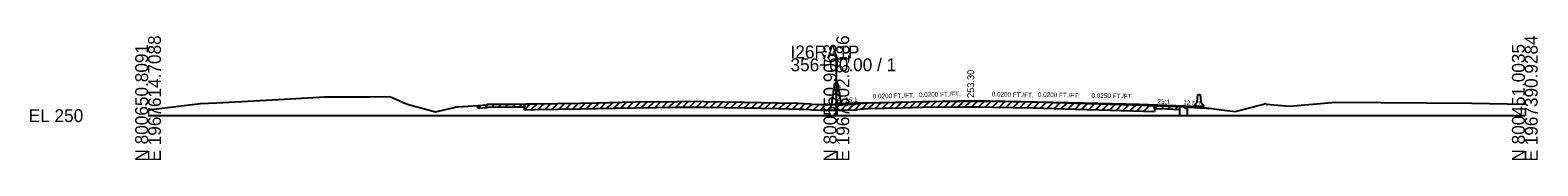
# Model space of a CAD drawing. Extents: x -26 to 304, y -10 to 7527.
# Drawn here: x -25.7 to 302.8, y 2990.3 to 3017.4 of the extents above; entities that cross this region are included whole.
import ezdxf

# ---------------------------------------------------------------- set-up
doc = ezdxf.new("R2010")
doc.units = 0
for name, color, linetype in [('Default', 7, 'Continuous'), ('RD_GPK_XS_Cell', 7, 'Continuous'), ('RD_XS_Base', 7, 'Continuous'), ('RD_XS_Box', 7, 'Continuous'), ('RD_XS_EarthShd', 7, 'Continuous'), ('RD_XS_ExGround', 7, 'Continuous'), ('RD_XS_ExPaveRet', 7, 'Continuous'), ('RD_XS_Misc_Line', 7, 'Continuous'), ('RD_XS_Pave', 7, 'Continuous'), ('RD_XS_PaveShd', 7, 'Continuous'), ('RD_XS_TX_Elev_EX', 7, 'Continuous'), ('RD_XS_TX_Elev_PR', 7, 'Continuous'), ('RD_XS_TX_Misc', 7, 'Continuous'), ('RD_XS_TX_MkPT', 7, 'Continuous'), ('RD_XS_TX_Profile', 7, 'Continuous'), ('RD_XS_TX_Station', 7, 'Continuous')]:
    doc.layers.add(name, color=color, linetype=linetype)

msp = doc.modelspace()

# ---------------------------------------------------------------- linework, layer by layer
at = {"layer": 'Default'}
for p, q in [((228, 3002.21), (228.58, 3003.04)), ((228.58, 3003.04), (228.75, 3004.62)), ((228.75, 3004.62), (229.25, 3004.62)), ((229.25, 3004.62), (229.42, 3003.04)), ((229.42, 3003.04), (230, 3002.21)), ((228, 3001.96), (228, 3002.21)), ((230, 3001.96), (228, 3001.96)), ((230, 3002.21), (230, 3001.96))]:
    msp.add_line(p, q, dxfattribs=at)
at = {"layer": 'RD_GPK_XS_Cell'}
for p, q in [((150, 3000), (150, 3012.48)), ((0, 3000), (150, 3000)), ((150, 3000), (300, 3000))]:
    msp.add_line(p, q, dxfattribs=at)
at = {"layer": 'RD_XS_Base'}
for p, q in [((150, 3002.42), (150, 3002.58)), ((224.72, 3000.13), (226.5, 3000.06)), ((226, 3001.56), (226, 3002.12)), ((226.5, 3001.54), (226, 3001.56)), ((226.5, 3000.06), (226.5, 3001.54))]:
    msp.add_line(p, q, dxfattribs=at)
at = {"layer": 'RD_XS_Box'}
for p, q in [((228, 3001.96), (230, 3001.8)), ((230, 3001.8), (231.8, 3001.58))]:
    msp.add_line(p, q, dxfattribs=at)
at = {"layer": 'RD_XS_EarthShd'}
for p, q in [((149, 3002.6), (149.67, 3007.08)), ((150, 3007.08), (149.67, 3007.08)), ((150, 3007.08), (150.33, 3007.08)), ((151, 3002.6), (150.33, 3007.08)), ((226, 3002.12), (228, 3001.96))]:
    msp.add_line(p, q, dxfattribs=at)
at = {"layer": 'RD_XS_ExGround'}
msp.add_lwpolyline([(0, 3001.21), (0.7, 3001.31), (11.42, 3002.61), (14.96, 3002.81), (29.71, 3003.57), (38.43, 3004.06), (47.23, 3004.1), (48.29, 3004.1), (52.66, 3004.16), (55.97, 3002.72), (56.73, 3002.39), (62.67, 3000.85), (66.68, 3001.79), (67.03, 3001.89), (67.59, 3001.92), (71.89, 3002.23), (73.85, 3002.37), (74.07, 3002.48), (79.41, 3002.52), (82.36, 3002.54), (84.3, 3002.56), (94.27, 3002.71), (97.71, 3002.79), (106.11, 3002.98), (115.33, 3003.09), (117.93, 3003.12), (121.25, 3003.07), (129.9, 3002.92), (137.34, 3002.78), (141.8, 3002.69), (142.82, 3002.65), (144.31, 3002.59), (144.57, 3002.5), (146.63, 3002.45), (148.22, 3002.41), (150, 3002.42), (150.63, 3002.42), (151.19, 3002.43), (154.21, 3002.53), (154.45, 3002.62), (155.13, 3002.66), (156.93, 3002.77), (164.02, 3002.95), (168.74, 3003.07), (177.62, 3003.15), (180.98, 3003.18), (184.24, 3003.12), (192.83, 3002.97), (202.08, 3002.69), (204.63, 3002.62), (207.15, 3002.54), (216.91, 3002.25), (222.09, 3002.08), (224.72, 3001.99), (225.56, 3001.94), (231.8, 3001.58), (233.94, 3001.27), (236.91, 3000.89), (243.12, 3002.53), (243.42, 3002.61), (243.65, 3002.48), (248.71, 3002.09), (258.85, 3002.96), (288.42, 3002.72), (300, 3002.47)], dxfattribs=at)
at = {"layer": 'RD_XS_ExPaveRet'}
for p, q in [((71.89, 3001.6), (71.89, 3002.23)), ((71.89, 3001.6), (73.85, 3001.75)), ((73.85, 3001.75), (74.07, 3001.86)), ((74.07, 3001.86), (79.41, 3001.89)), ((79.41, 3001.89), (82, 3001.91)), ((82, 3001.28), (82, 3002.53)), ((82, 3002.53), (82, 3001.91)), ((82, 3001.28), (82.36, 3001.29)), ((82.36, 3001.29), (84.3, 3001.31)), ((84.3, 3001.31), (94.27, 3001.46)), ((94.27, 3001.46), (97.71, 3001.54)), ((97.71, 3001.54), (106.11, 3001.73)), ((106.11, 3001.73), (115.33, 3001.84)), ((115.33, 3001.84), (117.93, 3001.87)), ((117.93, 3001.87), (121.25, 3001.82)), ((121.25, 3001.82), (129.9, 3001.67)), ((129.9, 3001.67), (137.34, 3001.53)), ((137.34, 3001.53), (141.8, 3001.44)), ((141.8, 3001.44), (142.82, 3001.4)), ((142.82, 3001.4), (144.31, 3001.34)), ((144.31, 3001.34), (144.57, 3001.25)), ((144.57, 3001.25), (146.63, 3001.2)), ((146.63, 3001.2), (148.22, 3001.16)), ((148.22, 3001.16), (150, 3001.17)), ((150, 3001.17), (150.63, 3001.17)), ((150.63, 3001.17), (151.19, 3001.18)), ((151.19, 3001.18), (154.21, 3001.28)), ((154.21, 3001.28), (154.45, 3001.37)), ((154.45, 3001.37), (155.13, 3001.41)), ((155.13, 3001.41), (156.93, 3001.52)), ((156.93, 3001.52), (164.02, 3001.7)), ((164.02, 3001.7), (168.74, 3001.82)), ((168.74, 3001.82), (177.62, 3001.9)), ((177.62, 3001.9), (180.98, 3001.93)), ((180.98, 3001.93), (184.24, 3001.87)), ((184.24, 3001.87), (192.83, 3001.72)), ((192.83, 3001.72), (202.08, 3001.44)), ((202.08, 3001.44), (204.63, 3001.37)), ((204.63, 3001.37), (207.15, 3001.29)), ((207.15, 3001.29), (216.91, 3001)), ((216.91, 3001), (219.31, 3000.92)), ((219.31, 3002.17), (219.31, 3000.92)), ((219.31, 3001.55), (219.31, 3002.17)), ((219.31, 3001.55), (222.09, 3001.45)), ((222.09, 3001.45), (224.72, 3001.36)), ((224.72, 3001.99), (224.72, 3001.36))]:
    msp.add_line(p, q, dxfattribs=at)
at = {"layer": 'RD_XS_Misc_Line'}
for p, q in [((97, 3001.53), (98.28, 3002.81)), ((98.5, 3001.56), (99.78, 3002.84)), ((100, 3001.59), (101.28, 3002.87)), ((101.5, 3001.63), (102.78, 3002.91)), ((103, 3001.66), (104.28, 3002.94)), ((104.5, 3001.69), (105.78, 3002.97)), ((106, 3001.73), (107.27, 3002.99)), ((107.5, 3001.75), (108.77, 3003.01)), ((109, 3001.76), (110.27, 3003.03)), ((110.5, 3001.78), (111.77, 3003.05)), ((112, 3001.8), (113.27, 3003.07)), ((113.5, 3001.82), (114.77, 3003.09)), ((115, 3001.84), (116.26, 3003.1)), ((116.5, 3001.86), (117.76, 3003.12)), ((118, 3001.87), (119.23, 3003.1)), ((119.5, 3001.85), (120.73, 3003.08)), ((121, 3001.83), (122.23, 3003.06)), ((122.5, 3001.8), (123.73, 3003.03)), ((124, 3001.78), (125.23, 3003)), ((125.5, 3001.75), (126.73, 3002.98)), ((127, 3001.72), (128.23, 3002.95)), ((128.5, 3001.7), (129.73, 3002.93)), ((130, 3001.67), (131.23, 3002.9)), ((131.5, 3001.64), (132.73, 3002.87)), ((133, 3001.62), (134.23, 3002.84)), ((134.5, 3001.59), (135.73, 3002.81)), ((157, 3001.52), (158.28, 3002.8)), ((158.5, 3001.56), (159.78, 3002.84)), ((160, 3001.59), (161.28, 3002.88)), ((161.5, 3001.63), (162.78, 3002.91)), ((163, 3001.67), (164.28, 3002.95)), ((164.5, 3001.71), (165.78, 3002.99)), ((166, 3001.75), (167.28, 3003.03)), ((167.5, 3001.79), (168.78, 3003.07)), ((169, 3001.82), (170.26, 3003.08)), ((170.5, 3001.84), (171.76, 3003.1)), ((172, 3001.85), (173.26, 3003.11)), ((173.5, 3001.86), (174.76, 3003.12)), ((175, 3001.88), (176.26, 3003.14)), ((176.5, 3001.89), (177.76, 3003.15)), ((178, 3001.9), (179.26, 3003.17)), ((179.5, 3001.92), (180.76, 3003.18)), ((181, 3001.93), (182.23, 3003.16)), ((182.5, 3001.9), (183.73, 3003.13)), ((184, 3001.88), (185.23, 3003.1)), ((185.5, 3001.85), (186.73, 3003.08)), ((187, 3001.82), (188.23, 3003.05)), ((188.5, 3001.8), (189.73, 3003.03)), ((190, 3001.77), (191.23, 3003)), ((191.5, 3001.75), (192.73, 3002.97)), ((193, 3001.72), (194.21, 3002.93)), ((194.5, 3001.67), (195.71, 3002.88)), ((196, 3001.63), (197.21, 3002.84)), ((197.5, 3001.58), (198.71, 3002.79)), ((71.89, 3001.6), (72.56, 3002.28)), ((73.39, 3001.71), (74.16, 3002.49)), ((74.89, 3001.86), (75.52, 3002.49)), ((76.39, 3001.87), (77.02, 3002.5)), ((77.89, 3001.88), (78.52, 3002.51)), ((79.39, 3001.89), (80.02, 3002.52)), ((80.89, 3001.9), (81.52, 3002.53)), ((82, 3001.28), (83.26, 3002.55)), ((83.5, 3001.3), (84.77, 3002.57)), ((85, 3001.32), (86.27, 3002.59)), ((86.5, 3001.34), (87.77, 3002.61)), ((88, 3001.37), (89.27, 3002.64)), ((89.5, 3001.39), (90.77, 3002.66)), ((91, 3001.41), (92.27, 3002.68)), ((92.5, 3001.43), (93.77, 3002.7)), ((94, 3001.46), (95.28, 3002.74)), ((95.5, 3001.49), (96.78, 3002.77)), ((136, 3001.56), (137.23, 3002.78)), ((137.5, 3001.53), (138.72, 3002.75)), ((139, 3001.5), (140.22, 3002.72)), ((140.5, 3001.47), (141.72, 3002.69)), ((142, 3001.43), (143.2, 3002.64)), ((143.5, 3001.38), (144.62, 3002.5)), ((145, 3001.24), (146.22, 3002.46)), ((146.5, 3001.21), (147.71, 3002.42)), ((148, 3001.16), (149.25, 3002.41)), ((149.5, 3001.16), (150.76, 3002.42)), ((151, 3001.18), (152.29, 3002.47)), ((152.5, 3001.22), (153.79, 3002.52)), ((154, 3001.28), (155.4, 3002.68)), ((155.5, 3001.43), (156.83, 3002.76)), ((199, 3001.53), (200.21, 3002.75)), ((200.5, 3001.49), (201.71, 3002.7)), ((202, 3001.44), (203.21, 3002.66)), ((203.5, 3001.4), (204.71, 3002.61)), ((205, 3001.35), (206.21, 3002.57)), ((206.5, 3001.31), (207.71, 3002.52)), ((208, 3001.26), (209.21, 3002.48)), ((209.5, 3001.22), (210.71, 3002.44)), ((211, 3001.18), (212.21, 3002.39)), ((212.5, 3001.13), (213.71, 3002.35)), ((214, 3001.09), (215.21, 3002.3)), ((215.5, 3001.04), (216.71, 3002.26)), ((217, 3001), (218.21, 3002.21)), ((219.31, 3001.55), (219.91, 3002.15)), ((220.81, 3001.5), (221.41, 3002.1)), ((222.31, 3001.45), (222.91, 3002.05)), ((223.81, 3001.39), (224.41, 3002))]:
    msp.add_line(p, q, dxfattribs=at)
at = {"layer": 'RD_XS_Pave'}
for p, q in [((156, 3002.82), (180, 3003.3)), ((180, 3003.3), (204, 3002.82)), ((204, 3002.82), (216, 3002.52))]:
    msp.add_line(p, q, dxfattribs=at)
at = {"layer": 'RD_XS_PaveShd'}
for p, q in [((156, 3002.82), (150, 3002.58)), ((216, 3002.52), (226, 3002.12))]:
    msp.add_line(p, q, dxfattribs=at)
at = {"layer": 'RD_XS_TX_Elev_PR'}
for p, q in [((156.93, 3002.77), (164.02, 3002.95)), ((164.02, 3002.95), (168.74, 3003.07)), ((168.74, 3003.07), (177.62, 3003.15)), ((177.62, 3003.15), (180.98, 3003.18)), ((180.98, 3003.18), (184.24, 3003.12)), ((184.24, 3003.12), (192.83, 3002.97)), ((192.83, 3002.97), (202.08, 3002.69)), ((150, 3002.42), (150.63, 3002.42)), ((150.63, 3002.42), (151.19, 3002.43)), ((151.19, 3002.43), (154.21, 3002.53)), ((154.21, 3002.53), (154.45, 3002.62)), ((154.45, 3002.62), (155.13, 3002.66)), ((155.13, 3002.66), (156.93, 3002.77)), ((202.08, 3002.69), (204.63, 3002.62)), ((204.63, 3002.62), (207.15, 3002.54)), ((207.15, 3002.54), (216.91, 3002.25)), ((216.91, 3002.25), (219.31, 3002.17)), ((219.31, 3002.17), (223.4, 3002.03)), ((223.4, 3002.03), (224.72, 3001.99)), ((224.72, 3001.99), (224.72, 3000.13))]:
    msp.add_line(p, q, dxfattribs=at)

# ---------------------------------------------------------------- texts
at = {"layer": 'RD_GPK_XS_Cell'}
for s, p in [('E 1967614.7088', (2.8, 2990)), ('E 1967502.8186', (152.8, 2990)), ('E 1967390.9284', (302.8, 2990)), ('N 800650.8091', (0, 2990)), ('N 800550.9063', (150, 2990)), ('N 800451.0035', (300, 2990))]:
    msp.add_text(s, height=2.8, rotation=90, dxfattribs=at).set_placement(p)
for s, p in [('I26RA1P', (140, 3012.48)), ('356+00.00 / 1', (140, 3009.68)), ('EL 250', (-26, 2998.6))]:
    msp.add_text(s, height=2.8, dxfattribs=at).set_placement(p)
at = {"layer": 'RD_XS_TX_Elev_EX'}
msp.add_text('252.42', height=1, rotation=90, dxfattribs=at).set_placement((151, 3002.42))
at = {"layer": 'RD_XS_TX_Misc'}
msp.add_text('12.5:1', height=1, rotation=355.4261, dxfattribs=at).set_placement((225.54, 3002.4))
at = {"layer": 'RD_XS_TX_MkPT'}
for rotation, p in [(2.2906, (151.94, 3002.9)), (357.7094, (219.96, 3002.61))]:
    msp.add_text('25:1', height=1, rotation=rotation, dxfattribs=at).set_placement(p)
at = {"layer": 'RD_XS_TX_Profile'}
for s, rotation, p in [('0.0200 FT./FT.', 1.1458, (157.92, 3003.74)), ('0.0200 FT./FT.', 1.1458, (167.98, 3004.06)), ('0.0200 FT./FT.', 358.5679, (183.83, 3004.2)), ('0.0200 FT./FT.', 358.8542, (193.89, 3004.1)), ('0.0250 FT./FT.', 358.8542, (205.57, 3003.9))]:
    msp.add_text(s, height=1, rotation=rotation, dxfattribs=at).set_placement(p)
at = {"layer": 'RD_XS_TX_Station'}
msp.add_text(' 253.30', height=1.5, rotation=90, dxfattribs=at).set_placement((180, 3003.3))

doc.saveas('drawing.dxf')
